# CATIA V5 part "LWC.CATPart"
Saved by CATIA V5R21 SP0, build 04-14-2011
Part number: LWC.SLDPRT
Bounding box of the stored display mesh (mm): x -1.7 to 1.7, y -1.65 to 1.65, z -1.105 to 0.8
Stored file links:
  C:\Users\user\Desktop\CATIA文件\0-最新文件\LWC\LWC.CATPart
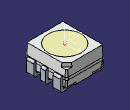
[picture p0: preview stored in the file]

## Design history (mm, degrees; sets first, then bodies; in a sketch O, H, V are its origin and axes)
AxisSystem1: origin (-0.0013, 0.0024, 0.8), X (0, 1, 0), Y (-1, 0, 0), Z (0, 0, 1)
Set1
  DatumSurface1 to DatumSurface138
  Circle1: stored without definition
  Circle2: stored without definition
  DatumCurve1 to DatumCurve5
  Line1 to Line5: stored without definition
  DatumCurve6 to DatumCurve12
  Line6: stored without definition
  Circle3 to Circle8: stored without definition
  Line7: stored without definition
  Circle9: stored without definition
  Line8: stored without definition
  Circle10: stored without definition
  Line9: stored without definition
  Circle11: stored without definition
  Line10: stored without definition
  Circle12: stored without definition
  Line11 to Line13: stored without definition
  Circle13: stored without definition
  Line14: stored without definition
  Circle14: stored without definition
  Line15 to Line23: stored without definition
  Circle15: stored without definition
  Line24: stored without definition
  Circle16: stored without definition
  Line25 to Line27: stored without definition
  Circle17: stored without definition
  Line28: stored without definition
  Circle18: stored without definition
  Line29 to Line40: stored without definition
  Circle19: stored without definition
  Line41: stored without definition
  Circle20: stored without definition
  Line42 to Line44: stored without definition
  Circle21: stored without definition
  Line45: stored without definition
  Circle22: stored without definition
  Line46 to Line54: stored without definition
  Circle23: stored without definition
  Line55: stored without definition
  Circle24: stored without definition
  Line56 to Line58: stored without definition
  Circle25: stored without definition
  Line59: stored without definition
  Circle26: stored without definition
  Line60 to Line65: stored without definition
  Circle27 to Circle29: stored without definition
  Line66: stored without definition
  Circle30: stored without definition
  Line67: stored without definition
  Circle31: stored without definition
  Line68: stored without definition
  Circle32: stored without definition
  Line69: stored without definition
  Circle33 to Circle38: stored without definition
  Line70: stored without definition
  Line71: stored without definition
  Circle39: stored without definition
  Circle40: stored without definition
  Line72 to Line78: stored without definition
  DatumCurve13
  DatumCurve14
  Line79: stored without definition
  Line80: stored without definition
  Circle41: stored without definition
  Line81: stored without definition
  DatumCurve15
  Line82: stored without definition
  Line83: stored without definition
  DatumCurve16
  Line84: stored without definition
  Circle42: stored without definition
  Line85: stored without definition
  DatumCurve17
  Line86: stored without definition
  DatumCurve18
  Line87 to Line89: stored without definition
  DatumCurve19
  DatumCurve20
  Line90: stored without definition
  Circle43: stored without definition
  Line91: stored without definition
  Circle44: stored without definition
  Circle45: stored without definition
  Line92: stored without definition
  Circle46 to Circle49: stored without definition
  Line93: stored without definition
  Circle50: stored without definition
  Line94 to Line99: stored without definition
  DatumCurve21
  Line100: stored without definition
  Circle51: stored without definition
  Line101: stored without definition
  Line102: stored without definition
  DatumCurve22
  Line103 to Line111: stored without definition
  DatumCurve23
  Line112: stored without definition
  DatumCurve24
  Line113: stored without definition
  Circle52: stored without definition
  DatumCurve25
  Line114 to Line116: stored without definition
  Circle53: stored without definition
  Line117 to Line124: stored without definition
  DatumCurve26
  Line125: stored without definition
  DatumCurve27 to DatumCurve29
  Circle54: stored without definition
  Line126: stored without definition
  Circle55: stored without definition
  Line127 to Line129: stored without definition
  DatumCurve30
  Line130: stored without definition
  Line131: stored without definition
  DatumCurve31
  Line132 to Line139: stored without definition
  DatumCurve32
  Line140 to Line143: stored without definition
  DatumCurve33
  Line144 to Line169: stored without definition
  Circle56: stored without definition
  Line170: stored without definition
  Circle57: stored without definition
  Line171 to Line173: stored without definition
  Circle58: stored without definition
  Line174: stored without definition
  Circle59: stored without definition
  Line175 to Line183: stored without definition
  Circle60: stored without definition
  Line184: stored without definition
  Circle61: stored without definition
  Line185 to Line187: stored without definition
  Circle62: stored without definition
  Circle63: stored without definition
  Line188: stored without definition
  Circle64: stored without definition
  Circle65: stored without definition
  Line189 to Line191: stored without definition
  Circle66: stored without definition
  Line192: stored without definition
  Circle67: stored without definition
  Line193 to Line201: stored without definition
  Circle68: stored without definition
  Line202: stored without definition
  Circle69: stored without definition
  Line203 to Line205: stored without definition
  Circle70: stored without definition
  Line206: stored without definition
  Circle71: stored without definition
  Line207: stored without definition
  Line208: stored without definition
  Circle72: stored without definition
  Line209: stored without definition
  Circle73: stored without definition
  Line210 to Line212: stored without definition
  Circle74: stored without definition
  Line213: stored without definition
  Circle75: stored without definition
  Line214 to Line216: stored without definition
  Circle76: stored without definition
  Line217 to Line219: stored without definition
  Circle77: stored without definition
  Line220 to Line227: stored without definition
  Circle78: stored without definition
  Line228: stored without definition
  Line229: stored without definition
  Circle79: stored without definition
  Line230: stored without definition
  Circle80: stored without definition
  Line231: stored without definition
  Circle81: stored without definition
  Line232 to Line234: stored without definition
  Circle82: stored without definition
  Line235: stored without definition
  Circle83: stored without definition
  Line236: stored without definition
  Circle84: stored without definition
  Line237 to Line239: stored without definition
  Circle85: stored without definition
  Line240 to Line245: stored without definition
  Circle86: stored without definition
  Line246 to Line248: stored without definition
  Circle87: stored without definition
  Line249: stored without definition
  Line250: stored without definition
  Circle88: stored without definition
  Point1 "几何中心&发光中心（测试原点）": type Center, Curve edge of DatumSurface70
  Point2: (0.0137, -0.003, -0.0777), relative to Point1, in AxisSystem1
Body1 (main body)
